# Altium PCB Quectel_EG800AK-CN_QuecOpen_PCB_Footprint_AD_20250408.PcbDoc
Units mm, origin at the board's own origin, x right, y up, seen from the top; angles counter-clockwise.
Board outline 152.4 x 101.6 mm, 2 copper layers (Top Layer, Bottom Layer); 1 components, 0 nets, 109 pads, 0 vias.
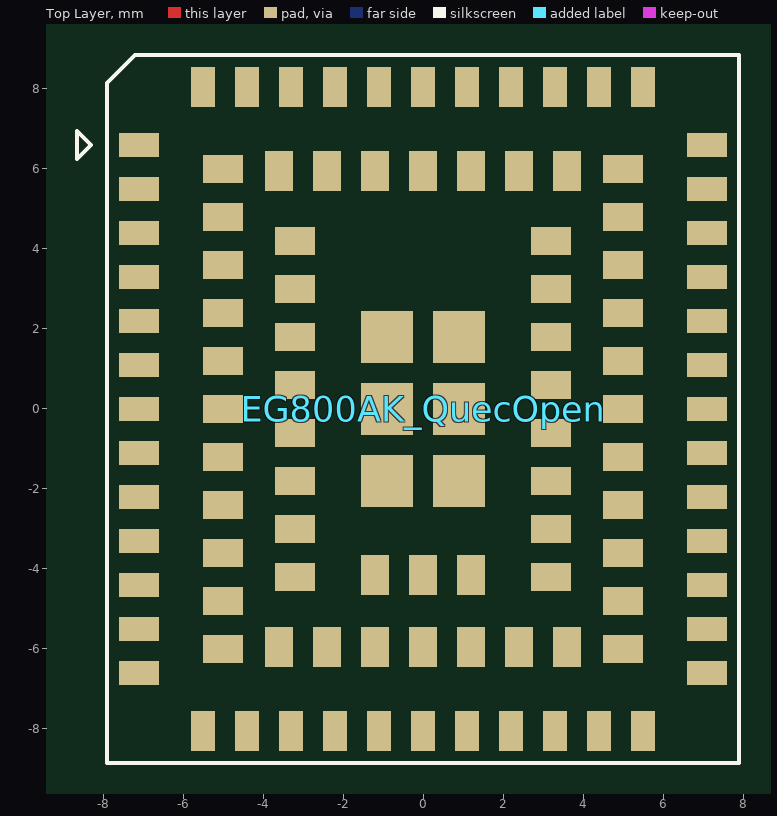
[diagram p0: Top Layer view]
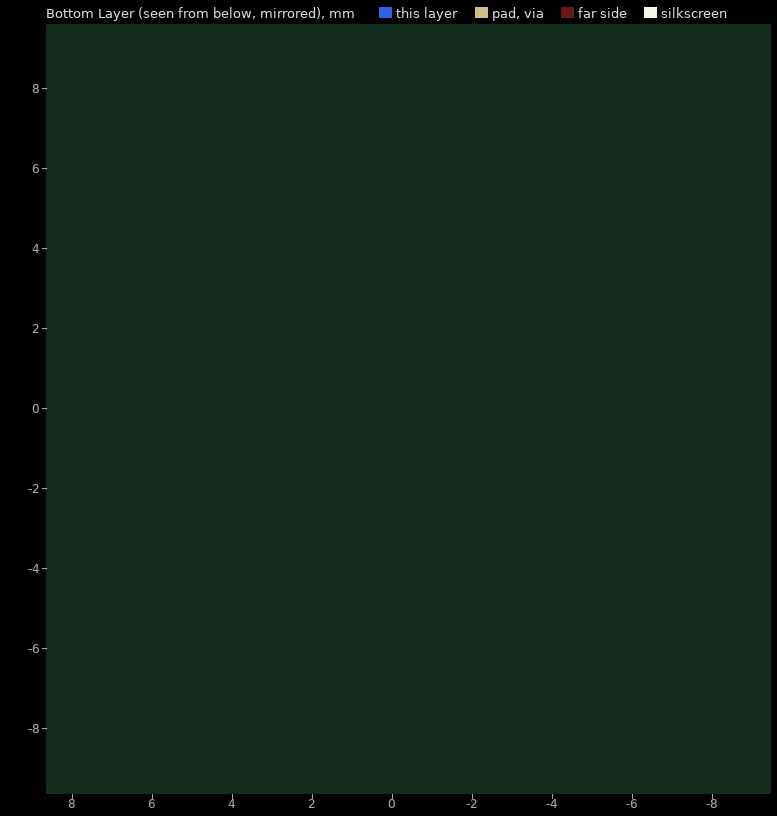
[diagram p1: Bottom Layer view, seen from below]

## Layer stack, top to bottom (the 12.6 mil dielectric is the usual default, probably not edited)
Top Solder: solder mask 0.0102, Solder Resist, Dk 3.5
Top Layer: signal copper 0.0356
Dielectric1: dielectric 0.32, FR-4, Dk 4.8
Bottom Layer: signal copper 0.0356
Bottom Solder: solder mask 0.0102, Solder Resist, Dk 3.5

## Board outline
-70.739,-53.721 81.661,-53.721 81.661,47.879 -70.739,47.879

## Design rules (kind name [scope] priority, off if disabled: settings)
Clearance [All] p1: gap=0.254 ignorepadtopadclearanceinfootprint=FALSE except(0: Arc-Hole Track-Hole SMDPad-Hole THPad-Hole Via-Hole Fill-Hole Poly-Hole Region-Hole Text-Hole)
PolygonConnect [All] p1: connectstyle=Relief reliefconductorwidth=0.254 reliefentries=4 polygonreliefangle="90 Angle" airgapwidth=0.254
RoutingVias [All] p1: holewidth=0.711 width=1.27 viastyle="Through Hole" minholewidth=0.711 minwidth=1.27 maxholewidth=0.711 maxwidth=1.27
SilkToSolderMaskClearance [IsPad] p1 off: minsilkscreentomaskgap=0.254 clearancetoexposedcopper=TRUE
SolderMaskExpansion [All] p1: expansion=0.102 istentingtop=FALSE
Width [All] p1: maxlimit=0.254 minlimit=0.254 preferedwidth=0.254
29 further rules are at their usual default settings.

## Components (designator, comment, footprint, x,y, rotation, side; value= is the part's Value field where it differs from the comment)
EG800AK_QuecOpen "Comment" EG800AK_QuecOpen 0,0 r0 top

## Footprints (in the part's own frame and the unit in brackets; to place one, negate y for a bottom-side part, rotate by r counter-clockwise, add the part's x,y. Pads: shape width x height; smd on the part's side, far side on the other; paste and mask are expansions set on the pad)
EG800AK_QuecOpen [mm] "EG800AK-CN QuecOpen Module 109PIN 17.7X15.8mm H2.4mm RO"
  rect 1x0.6 smd mask+0.05: 1(-7.1,6.6) 2(-7.1,5.5) 3(-7.1,4.4) 4(-7.1,3.3) 5(-7.1,2.2) 6(-7.1,1.1) 7(-7.1,0) 8(-7.1,-1.1) 9(-7.1,-2.2) 10(-7.1,-3.3) 11(-7.1,-4.4) 12(-7.1,-5.5) 13(-7.1,-6.6) 23(7.1,-6.6) 24(7.1,-5.5) 25(7.1,-4.4) 26(7.1,-3.3) 27(7.1,-2.2) 28(7.1,-1.1) 29(7.1,0) 30(7.1,1.1) 31(7.1,2.2) 32(7.1,3.3) 33(7.1,4.4) 34(7.1,5.5) 35(7.1,6.6)
  rect 0.6x1 smd mask+0.05: 14(-4.4,-8.05) 15(-3.3,-8.05) 16(-2.2,-8.05) 17(-1.1,-8.05) 18(0,-8.05) 19(1.1,-8.05) 20(2.2,-8.05) 21(3.3,-8.05) 22(4.4,-8.05) 36(4.4,8.05) 37(3.3,8.05) 38(2.2,8.05) 39(1.1,8.05) 40(0,8.05) 41(-1.1,8.05) 42(-2.2,8.05) 43(-3.3,8.05) 44(-4.4,8.05) 95(-5.5,-8.05) 96(5.5,-8.05) 97(5.5,8.05) 98(-5.5,8.05)
  rect 1x0.7 smd mask+0.05: 45(-5,4.8) 46(-5,3.6) 47(-5,2.4) 48(-5,1.2) 49(-5,0) 50(-5,-1.2) 51(-5,-2.4) 52(-5,-3.6) 53(-5,-4.8) 59(5,-4.8) 60(5,-3.6) 61(5,-2.4) 62(5,-1.2) 63(5,0) 64(5,1.2) 65(5,2.4) 66(5,3.6) 67(5,4.8) 73(-3.2,4.2) 74(-3.2,3) 75(-3.2,1.8) 76(-3.2,0.6) 77(-3.2,-0.6) 78(-3.2,-1.8) 79(-3.2,-3) 80(-3.2,-4.2) 81(3.2,-4.2) 82(3.2,-3) 83(3.2,-1.8) 84(3.2,-0.6) 85(3.2,0.6) 86(3.2,1.8) 87(3.2,3) 88(3.2,4.2) 99(-5,6) 100(-5,-6) 103(5,-6) 104(5,6)
  rect 0.7x1 smd mask+0.05: 54(-2.4,-5.95) 55(-1.2,-5.95) 56(0,-5.95) 57(1.2,-5.95) 58(2.4,-5.95) 68(2.4,5.95) 69(1.2,5.95) 70(0,5.95) 71(-1.2,5.95) 72(-2.4,5.95) 101(-3.6,-5.95) 102(3.6,-5.95) 105(3.6,5.95) 106(-3.6,5.95) 107(-1.2,-4.15) 108(0,-4.15) 109(1.2,-4.15)
  rect 1.3x1.3 smd mask+0.05: 89(-0.9,1.8) 90(-0.9,0) 91(-0.9,-1.8) 92(0.9,-1.8) 93(0.9,0) 94(0.9,1.8)
  silkscreen extent -8.65,-8.85 7.9,8.85, body extent -7.9,-8.85 7.9,8.85, height 2.4

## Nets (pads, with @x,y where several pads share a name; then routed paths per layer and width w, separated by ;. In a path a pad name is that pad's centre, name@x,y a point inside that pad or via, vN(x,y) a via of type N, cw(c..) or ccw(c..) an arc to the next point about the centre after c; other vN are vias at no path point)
pads on no net: EG800AK_QuecOpen.1 EG800AK_QuecOpen.2 EG800AK_QuecOpen.3 EG800AK_QuecOpen.4 EG800AK_QuecOpen.5 EG800AK_QuecOpen.6 EG800AK_QuecOpen.7 EG800AK_QuecOpen.8 EG800AK_QuecOpen.9 EG800AK_QuecOpen.10 EG800AK_QuecOpen.11 EG800AK_QuecOpen.12 EG800AK_QuecOpen.13 EG800AK_QuecOpen.14 EG800AK_QuecOpen.15 EG800AK_QuecOpen.16 EG800AK_QuecOpen.17 EG800AK_QuecOpen.18 EG800AK_QuecOpen.19 EG800AK_QuecOpen.20 EG800AK_QuecOpen.21 EG800AK_QuecOpen.22 EG800AK_QuecOpen.23 EG800AK_QuecOpen.24 EG800AK_QuecOpen.25 EG800AK_QuecOpen.26 EG800AK_QuecOpen.27 EG800AK_QuecOpen.28 EG800AK_QuecOpen.29 EG800AK_QuecOpen.30 EG800AK_QuecOpen.31 EG800AK_QuecOpen.32 EG800AK_QuecOpen.33 EG800AK_QuecOpen.34 EG800AK_QuecOpen.35 EG800AK_QuecOpen.36 EG800AK_QuecOpen.37 EG800AK_QuecOpen.38 EG800AK_QuecOpen.39 EG800AK_QuecOpen.40 EG800AK_QuecOpen.41 EG800AK_QuecOpen.42 EG800AK_QuecOpen.43 EG800AK_QuecOpen.44 EG800AK_QuecOpen.45 EG800AK_QuecOpen.46 EG800AK_QuecOpen.47 EG800AK_QuecOpen.48 EG800AK_QuecOpen.49 EG800AK_QuecOpen.50 EG800AK_QuecOpen.51 EG800AK_QuecOpen.52 EG800AK_QuecOpen.53 EG800AK_QuecOpen.54 EG800AK_QuecOpen.55 EG800AK_QuecOpen.56 EG800AK_QuecOpen.57 EG800AK_QuecOpen.58 EG800AK_QuecOpen.59 EG800AK_QuecOpen.60 EG800AK_QuecOpen.61 EG800AK_QuecOpen.62 EG800AK_QuecOpen.63 EG800AK_QuecOpen.64 EG800AK_QuecOpen.65 EG800AK_QuecOpen.66 EG800AK_QuecOpen.67 EG800AK_QuecOpen.68 EG800AK_QuecOpen.69 EG800AK_QuecOpen.70 EG800AK_QuecOpen.71 EG800AK_QuecOpen.72 EG800AK_QuecOpen.73 EG800AK_QuecOpen.74 EG800AK_QuecOpen.75 EG800AK_QuecOpen.76 EG800AK_QuecOpen.77 EG800AK_QuecOpen.78 EG800AK_QuecOpen.79 EG800AK_QuecOpen.80 EG800AK_QuecOpen.81 EG800AK_QuecOpen.82 EG800AK_QuecOpen.83 EG800AK_QuecOpen.84 EG800AK_QuecOpen.85 EG800AK_QuecOpen.86 EG800AK_QuecOpen.87 EG800AK_QuecOpen.88 EG800AK_QuecOpen.89 EG800AK_QuecOpen.90 EG800AK_QuecOpen.91 EG800AK_QuecOpen.92 EG800AK_QuecOpen.93 EG800AK_QuecOpen.94 EG800AK_QuecOpen.95 EG800AK_QuecOpen.96 EG800AK_QuecOpen.97 EG800AK_QuecOpen.98 EG800AK_QuecOpen.99 EG800AK_QuecOpen.100 EG800AK_QuecOpen.101 EG800AK_QuecOpen.102 EG800AK_QuecOpen.103 EG800AK_QuecOpen.104 EG800AK_QuecOpen.105 EG800AK_QuecOpen.106 EG800AK_QuecOpen.107 EG800AK_QuecOpen.108 EG800AK_QuecOpen.109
